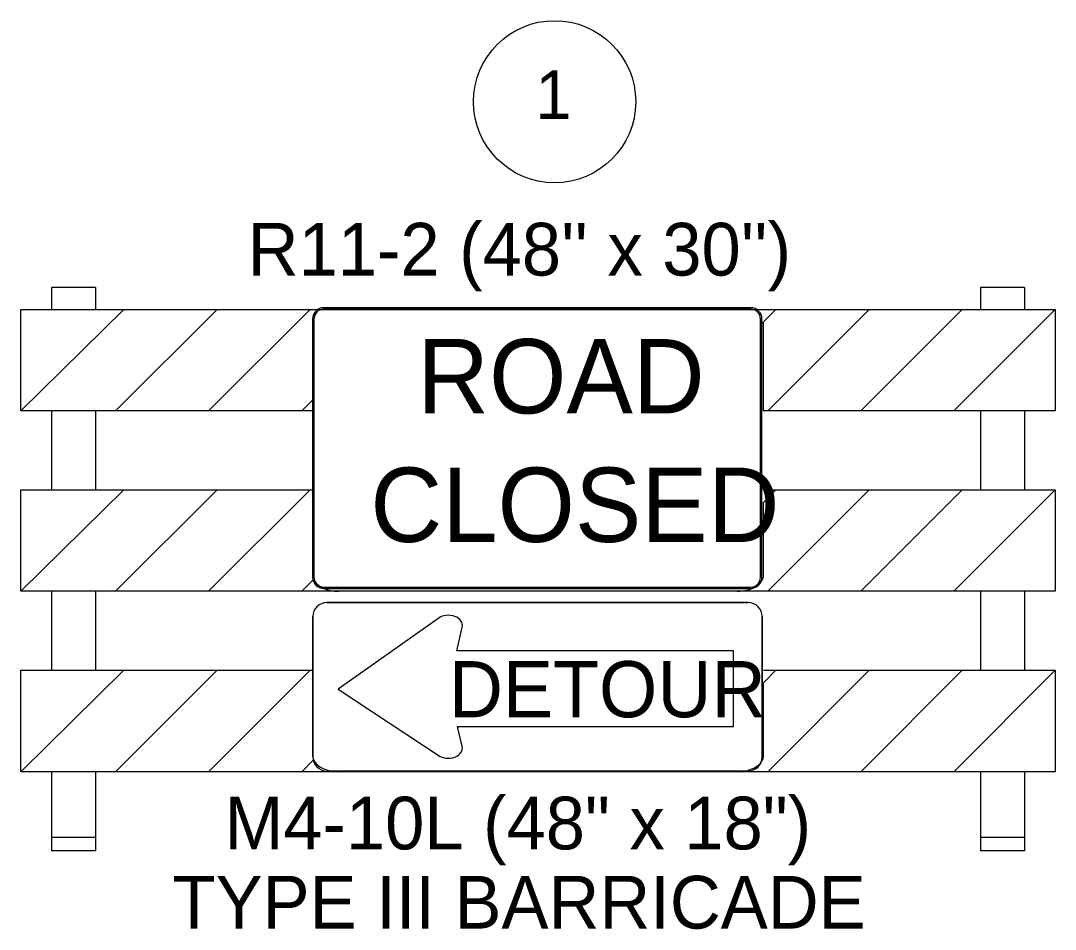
# Model space of a CAD drawing. Extents: x 886234 to 968767, y 455416 to 684046.
# Drawn here: x 912317 to 914717, y 517802 to 519910 of the extents above; entities that cross this region are included whole.
import ezdxf

# ---------------------------------------------------------------- set-up
doc = ezdxf.new("R2010")
doc.units = 0
for name, color, linetype in [('TC DEV BARRICADE', 7, 'Continuous'), ('TC DEV SIGN BLACK 239', 7, 'Continuous'), ('TC DEV SIGN BLACK ZERO', 7, 'Continuous'), ('TC DEV SIGN ORANGE', 7, 'Continuous'), ('TC DEV SIGN WHITE', 7, 'Continuous'), ('TC LABEL TEXT', 7, 'Continuous')]:
    doc.layers.add(name, color=color, linetype=linetype)

msp = doc.modelspace()

# ---------------------------------------------------------------- linework, layer by layer
at = {"layer": 'TC DEV BARRICADE'}
for p, q in [((912489.8, 519291.1), (912387.9, 519291.1)), ((912387.9, 519291.1), (912387.9, 519240.2)), ((912489.8, 519291.1), (912489.8, 519240.2)), ((914645.3, 519291.1), (914543.4, 519291.1)), ((914543.4, 519291.1), (914543.4, 519240.2)), ((914645.3, 519291.1), (914645.3, 519240.2)), ((912316.6, 519240.2), (914716.6, 519240.2)), ((912316.6, 519004.8), (912316.6, 519240.2)), ((912316.6, 519004.8), (912316.6, 519240.2)), ((912316.6, 519240.2), (912556, 519240.2)), ((912556, 519240.2), (912316.6, 519004.8)), ((912536.7, 519004.8), (912772, 519240.2)), ((912987.9, 519240.2), (912752.6, 519004.8)), ((912772, 519240.2), (912987.9, 519240.2)), ((914038.5, 519209.9), (914068.7, 519240.2)), ((914284.7, 519240.2), (914049.4, 519004.8)), ((914068.7, 519240.2), (914284.7, 519240.2)), ((914265.3, 519004.8), (914500.7, 519240.2)), ((914716.6, 519240.2), (914481.3, 519004.8)), ((914500.7, 519240.2), (914716.6, 519240.2)), ((914716.6, 519240.2), (914716.6, 519004.8)), ((914039.8, 519004.8), (914039.8, 519202)), ((912968.6, 519004.8), (912993.4, 519029.7)), ((912993.4, 519029.7), (912993.4, 519004.8)), ((912993.4, 519004.8), (912316.6, 519004.8)), ((912387.9, 519004.8), (912387.9, 518821.5)), ((912489.8, 519004.8), (912489.8, 518821.5)), ((912752.6, 519004.8), (912536.7, 519004.8)), ((912993.4, 519004.8), (912968.6, 519004.8)), ((914049.4, 519004.8), (914039.8, 519004.8)), ((914716.6, 519004.8), (914039.8, 519004.8)), ((914481.3, 519004.8), (914265.3, 519004.8)), ((914543.4, 519004.8), (914543.4, 518821.5)), ((914645.3, 519004.8), (914645.3, 518821.5)), ((912316.6, 518586.2), (912316.6, 518821.5)), ((912316.6, 518586.2), (912316.6, 518821.5)), ((912316.6, 518821.5), (912556, 518821.5)), ((912556, 518821.5), (912316.6, 518586.2)), ((912316.6, 518821.5), (912993.4, 518821.5)), ((912536.7, 518586.2), (912772, 518821.5)), ((912987.9, 518821.5), (912752.6, 518586.2)), ((912772, 518821.5), (912987.9, 518821.5)), ((914039.8, 518821.5), (914716.6, 518821.5)), ((914039.8, 518792.5), (914068.7, 518821.5)), ((914284.7, 518821.5), (914049.4, 518586.2)), ((914068.7, 518821.5), (914284.7, 518821.5)), ((914265.3, 518586.2), (914500.7, 518821.5)), ((914716.6, 518821.5), (914481.3, 518586.2)), ((914500.7, 518821.5), (914716.6, 518821.5)), ((914716.6, 518821.5), (914716.6, 518586.2)), ((914039.8, 518624.3), (914039.8, 518792.5)), ((912968.6, 518586.2), (912995.9, 518613.5)), ((914716.6, 518586.2), (912316.6, 518586.2)), ((912387.9, 518586.2), (912387.9, 518402.8)), ((912489.8, 518586.2), (912489.8, 518402.8)), ((912752.6, 518586.2), (912536.7, 518586.2)), ((913054.5, 518586.2), (912968.6, 518586.2)), ((914049.4, 518586.2), (913979.2, 518586.2)), ((914481.3, 518586.2), (914265.3, 518586.2)), ((914543.4, 518586.2), (914543.4, 518402.8)), ((914645.3, 518586.2), (914645.3, 518402.8)), ((912316.6, 518167.5), (912316.6, 518402.8)), ((912316.6, 518402.8), (912556, 518402.8)), ((912556, 518402.8), (912316.6, 518167.5)), ((912316.6, 518167.5), (912316.6, 518402.8)), ((912316.6, 518402.8), (912993.5, 518402.8)), ((912536.7, 518167.5), (912772, 518402.8)), ((912987.9, 518402.8), (912752.6, 518167.5)), ((912772, 518402.8), (912987.9, 518402.8)), ((914039.8, 518402.8), (914716.6, 518402.8)), ((914039.8, 518373.9), (914068.7, 518402.8)), ((914284.7, 518402.8), (914049.4, 518167.5)), ((914068.7, 518402.8), (914284.7, 518402.8)), ((914265.3, 518167.5), (914500.7, 518402.8)), ((914716.6, 518402.8), (914481.3, 518167.5)), ((914500.7, 518402.8), (914716.6, 518402.8)), ((914716.6, 518402.8), (914716.6, 518167.5)), ((914039.8, 518205.6), (914039.8, 518373.9)), ((912968.6, 518167.5), (912995.9, 518194.8)), ((914716.6, 518167.5), (912316.6, 518167.5)), ((912387.9, 518167.5), (912387.9, 517984.1)), ((912489.8, 518167.5), (912489.8, 517984.1)), ((912752.6, 518167.5), (912536.7, 518167.5)), ((913054.5, 518167.5), (912968.6, 518167.5)), ((914049.4, 518167.5), (913979.2, 518167.5)), ((914481.3, 518167.5), (914265.3, 518167.5)), ((914543.4, 518167.5), (914543.4, 517984.1)), ((914645.3, 518167.5), (914645.3, 517984.1)), ((912489.8, 518014.7), (912387.9, 518014.7)), ((914645.3, 518014.7), (914543.4, 518014.7)), ((912489.8, 517984.1), (912387.9, 517984.1)), ((914645.3, 517984.1), (914543.4, 517984.1))]:
    msp.add_line(p, q, dxfattribs=at)
for centre, major_axis, start_param, end_param in [((913978.8, 519202), (61, 0), 6.283185, 6.491582), ((913978.8, 518624.3), (-61, 0), 1.570796, 3.141593), ((913054.5, 518624.3), (-61, 0), 0.287132, 1.570688), ((913054.5, 518205.6), (-61, 0), 0.287132, 1.570688), ((913978.8, 518205.6), (-61, 0), 1.570796, 3.141593)]:
    msp.add_ellipse(centre, major_axis=major_axis, ratio=0.625, start_param=start_param, end_param=end_param, dxfattribs=at)
at = {"layer": 'TC DEV SIGN BLACK 239'}
msp.add_line((913019.8, 518592.7), (914010, 518592.6), dxfattribs=at)
for points in [[(914010, 519244), (913019.8, 519244)], [(912993.8, 519218), (912993.8, 518618.7)], [(914036, 518618.7), (914036, 519218)]]:
    msp.add_lwpolyline(points, dxfattribs=at)
for centre, start, end in [((913019.8, 519218), 90, 180), ((914010, 519218), 360, 90), ((913019.8, 518618.7), 180, 269.9991), ((914010, 518618.7), 269.9991, 0)]:
    msp.add_arc(centre, 26.1, start, end, dxfattribs=at)
at = {"layer": 'TC DEV SIGN BLACK ZERO'}
for p, q in [((913027, 518560), (914004.1, 518560)), ((912994.4, 518201.7), (912994.4, 518527.4)), ((913289.7, 518526.3), (913053.1, 518359)), ((914036.7, 518527.4), (914036.7, 518201.7)), ((913328.3, 518447.8), (913339.7, 518499.4)), ((913970.5, 518447.8), (913328.3, 518447.8)), ((913970.5, 518272.4), (913970.5, 518447.8)), ((913053.1, 518359), (913289.7, 518202.8)), ((913339.7, 518229.7), (913329.5, 518272.4)), ((913329.5, 518272.4), (913970.5, 518272.4)), ((914004.1, 518169.1), (913027, 518169.1))]:
    msp.add_line(p, q, dxfattribs=at)
for points in [[(914004.1, 518560), (913027, 518560)], [(912994.4, 518527.4), (912994.4, 518201.7)], [(914036.7, 518201.7), (914036.7, 518527.4)], [(913027, 518169.1), (914004.1, 518169.1)]]:
    msp.add_lwpolyline(points, dxfattribs=at)
for centre, start, end in [((913027, 518527.4), 90, 180), ((913027, 518527.4), 90, 180), ((914004.1, 518527.4), 0, 90), ((914004.1, 518527.4), 0, 90), ((913027, 518201.7), 180, 270), ((913027, 518201.7), 180, 270), ((914004.1, 518201.7), 270, 0), ((914004.1, 518201.7), 270, 0)]:
    msp.add_arc(centre, 32.6, start, end, dxfattribs=at)
for centre, start_param, end_param in [((913308.3, 518506.7), 2.830616, 5.313575), ((913308.3, 518222.4), 0.969609, 3.452568)]:
    msp.add_ellipse(centre, major_axis=(-33, 0), ratio=0.720018, start_param=start_param, end_param=end_param, dxfattribs=at)
at = {"layer": 'TC DEV SIGN ORANGE'}
for p, q in [((913289.7, 518526.3), (913053.1, 518359)), ((913328.3, 518447.8), (913339.7, 518499.4)), ((913970.5, 518447.8), (913328.3, 518447.8)), ((913970.5, 518272.4), (913970.5, 518447.8)), ((913053.1, 518359), (913289.7, 518202.8)), ((913339.7, 518229.7), (913329.5, 518272.4)), ((913329.5, 518272.4), (913970.5, 518272.4))]:
    msp.add_line(p, q, dxfattribs=at)
for centre, start_param, end_param in [((913308.3, 518506.7), 2.830616, 5.313575), ((913308.3, 518222.4), 0.969609, 3.452568)]:
    msp.add_ellipse(centre, major_axis=(-33, 0), ratio=0.720018, start_param=start_param, end_param=end_param, dxfattribs=at)
at = {"layer": 'TC DEV SIGN WHITE'}
msp.add_line((913019.8, 518595.9), (914010, 518595.9), dxfattribs=at)
for points in [[(914010, 519240.8), (913019.8, 519240.8)], [(912997, 519218), (912997, 518618.7)], [(914032.8, 518618.7), (914032.8, 519218)]]:
    msp.add_lwpolyline(points, dxfattribs=at)
for centre, start, end in [((913019.8, 519218), 90, 180), ((914010, 519218), 360, 90), ((913019.8, 518618.7), 180, 269.9991), ((914010, 518618.7), 269.9991, 0)]:
    msp.add_arc(centre, 22.8, start, end, dxfattribs=at)
at = {"layer": 'TC LABEL TEXT'}
msp.add_circle((913555.2, 519722.1), 188.1, dxfattribs=at)

# ---------------------------------------------------------------- texts
at = {"layer": 'TC DEV BARRICADE'}
for s, p in [("R11-2 (48'' x 30'')", (912843.2, 519318.8)), ('M4-10L (48" x 18")', (912789.6, 517987.3)), ('TYPE III BARRICADE', (912668.9, 517803.6))]:
    msp.add_text(s, height=122.241, dxfattribs=at).set_placement(p)
at = {"layer": 'TC DEV SIGN BLACK 239'}
for s, p in [('ROAD', (913236.4, 518998.9)), ('CLOSED', (913127.7, 518700.6))]:
    msp.add_text(s, height=172.62, dxfattribs=at).set_placement(p)
at = {"layer": 'TC DEV SIGN BLACK ZERO'}
msp.add_text('DETOUR', height=130.28, dxfattribs=at).set_placement((913309.6, 518293.9))
at = {"layer": 'TC LABEL TEXT'}
msp.add_text('1', height=112.5, dxfattribs=at).set_placement((913510.4, 519682.1))

doc.saveas('drawing.dxf')
